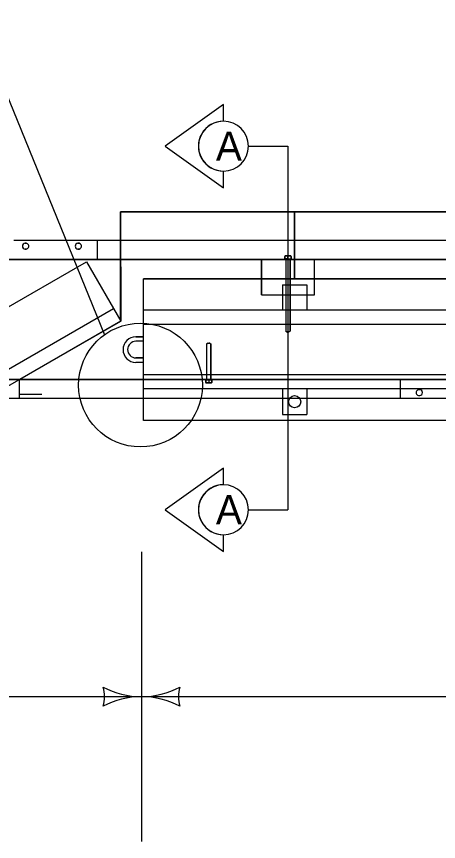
# Model space of a CAD drawing. Extents: x -2137026 to -2131464, y -2138478 to -2136524.
# Drawn here: x -2136746.1 to -2136526.6, y -2137925.1 to -2137495.8 of the extents above; entities that cross this region are included whole.
import ezdxf

# ---------------------------------------------------------------- set-up
doc = ezdxf.new("R2010")
doc.units = 0
for name, color, linetype in [('conPaving', 7, 'Continuous'), ('Level 2', 7, 'Continuous'), ('Level 3', 7, 'Continuous'), ('Level 41', 7, 'Continuous'), ('Level 9', 7, 'Continuous')]:
    doc.layers.add(name, color=color, linetype=linetype)

msp = doc.modelspace()

# ---------------------------------------------------------------- linework, layer by layer
at = {"layer": 'conPaving'}
for p, q in [((-2136462.32, -2137612.31), (-2136747.4, -2137612.31)), ((-2136741.63, -2137613.85), (-2136740.97, -2137613.85)), ((-2136740.97, -2137616.82), (-2136741.63, -2137616.82)), ((-2136714.21, -2137613.85), (-2136713.54, -2137613.85)), ((-2136713.54, -2137616.82), (-2136714.21, -2137616.82)), ((-2136606.45, -2137621.92), (-2136606.85, -2137621.92)), ((-2136606.85, -2137621.92), (-2136606.85, -2137622.22)), ((-2136606.45, -2137620.66), (-2136606.45, -2137621.92)), ((-2136604.57, -2137620.35), (-2136606.17, -2137620.35)), ((-2136603.55, -2137620.35), (-2136604.57, -2137620.35)), ((-2136603.26, -2137621.92), (-2136603.26, -2137620.66)), ((-2136602.87, -2137621.92), (-2136603.26, -2137621.92)), ((-2136602.87, -2137622.22), (-2136602.87, -2137621.92)), ((-2136768.45, -2137622.22), (-2136441.26, -2137622.22)), ((-2136606.85, -2137622.22), (-2136605.92, -2137622.22)), ((-2136605.92, -2137622.22), (-2136605.92, -2137659.5)), ((-2136603.8, -2137659.5), (-2136603.8, -2137622.22)), ((-2136603.8, -2137622.22), (-2136602.87, -2137622.22)), ((-2136605.92, -2137659.5), (-2136604.85, -2137660.28)), ((-2136604.85, -2137660.27), (-2136603.8, -2137659.5)), ((-2136604.85, -2137660.28), (-2136604.85, -2137660.25)), ((-2136604.85, -2137660.25), (-2136604.85, -2137660.27)), ((-2136683.95, -2137662.47), (-2136680.02, -2137662.47)), ((-2136647.12, -2137666.16), (-2136646.59, -2137665.78)), ((-2136647.12, -2137684.65), (-2136647.12, -2137666.16)), ((-2136646.59, -2137665.78), (-2136646.06, -2137665.78)), ((-2136646.06, -2137665.78), (-2136645.53, -2137665.78)), ((-2136645.53, -2137665.78), (-2136645, -2137666.16)), ((-2136645, -2137666.16), (-2136645, -2137684.65)), ((-2136680.02, -2137675.83), (-2136683.95, -2137675.83)), ((-2136809.17, -2137684.65), (-2136481.98, -2137684.65)), ((-2136648.05, -2137684.95), (-2136648.05, -2137684.65)), ((-2136648.05, -2137684.65), (-2136647.12, -2137684.65)), ((-2136647.65, -2137684.95), (-2136648.05, -2137684.95)), ((-2136647.65, -2137686.21), (-2136647.65, -2137684.95)), ((-2136645.77, -2137686.52), (-2136647.37, -2137686.52)), ((-2136644.75, -2137686.52), (-2136645.77, -2137686.52)), ((-2136645, -2137684.65), (-2136644.07, -2137684.65)), ((-2136644.07, -2137684.95), (-2136644.46, -2137684.95)), ((-2136644.46, -2137684.95), (-2136644.46, -2137686.21)), ((-2136644.07, -2137684.65), (-2136644.07, -2137684.95)), ((-2136536.22, -2137690.05), (-2136536.89, -2137690.05)), ((-2136503.04, -2137694.56), (-2136788.12, -2137694.56)), ((-2136536.89, -2137693.02), (-2136536.22, -2137693.02))]:
    msp.add_line(p, q, dxfattribs=at)
for points in [[(-2136680.02, -2137662.47), (-2136680.02, -2137632.29), (-2136601.44, -2137632.29), (-2136601.44, -2137597.41), (-2136691.9, -2137597.41), (-2136691.85, -2137654.33)], [(-2136691.85, -2137654.33), (-2136744.37, -2137684.65), (-2136680.02, -2137684.65), (-2136680.02, -2137675.83)]]:
    msp.add_lwpolyline(points, dxfattribs=at)
msp.add_arc((-2136683.95, -2137669.15), 6.68, 90, 270, dxfattribs=at)
for centre, major_axis, start_param, end_param in [((-2136741.63, -2137615.33), (0, -1.49), 3.141593, 6.283185), ((-2136740.97, -2137615.33), (0, -1.49), 0, 3.141593), ((-2136714.21, -2137615.33), (0, -1.49), 3.141593, 6.283185), ((-2136713.54, -2137615.33), (0, -1.49), 0, 3.141593), ((-2136606.17, -2137620.66), (0, 0.315), 0, 1.570796), ((-2136603.55, -2137620.66), (0, 0.315), 4.712389, 6.283185), ((-2136647.37, -2137686.21), (0, -0.315), 4.712389, 6.283185), ((-2136644.75, -2137686.21), (0, -0.315), 6.283185, 7.853982), ((-2136536.89, -2137691.53), (0, 1.49), 0, 3.141593), ((-2136536.22, -2137691.53), (0, 1.49), 3.141593, 6.283185)]:
    msp.add_ellipse(centre, major_axis=major_axis, ratio=0.899999, start_param=start_param, end_param=end_param, dxfattribs=at)
at = {"layer": 'Level 2'}
for p, q in [((-2136767.77, -2137495.85), (-2136700.29, -2137661.41)), ((-2136625.44, -2137563.31), (-2136604.87, -2137563.31)), ((-2136604.87, -2137563.31), (-2136604.87, -2137752.45)), ((-2136762.17, -2137653.8), (-2136709.66, -2137623.48)), ((-2136709.66, -2137623.48), (-2136691.85, -2137654.33)), ((-2136188.5, -2137632.29), (-2136680.02, -2137632.29)), ((-2136680.02, -2137706.01), (-2136680.02, -2137632.29)), ((-2136754.92, -2137682), (-2136695.64, -2137647.78)), ((-2136188.5, -2137648.67), (-2136680.02, -2137648.67)), ((-2136752.91, -2137689.58), (-2136691.85, -2137654.33)), ((-2136188.5, -2137656.04), (-2136680.02, -2137656.04)), ((-2136188.5, -2137682.26), (-2136680.02, -2137682.26)), ((-2136188.5, -2137689.63), (-2136680.02, -2137689.63)), ((-2136188.5, -2137706.01), (-2136680.02, -2137706.01)), ((-2136625.44, -2137752.45), (-2136604.87, -2137752.45)), ((-2136681.05, -2137774.34), (-2136681.05, -2137925.06)), ((-2136777.98, -2137849.7), (-2136681.05, -2137849.7)), ((-2136681.05, -2137849.7), (-2136429.72, -2137849.7))]:
    msp.add_line(p, q, dxfattribs=at)
for centre, radius, start, end in [((-2136716.68, -2137849.7), 16.42, 342.2667, 17.7334), ((-2136681.05, -2137807.2), 42.5, 241.9275, 270), ((-2136681.05, -2137807.2), 42.5, 270, 298.0725), ((-2136645.41, -2137849.7), 16.42, 162.2666, 197.7334), ((-2136681.05, -2137892.2), 42.5, 90, 118.0725), ((-2136681.05, -2137892.2), 42.5, 61.9275, 90)]:
    msp.add_arc(centre, radius, start, end, dxfattribs=at)
at = {"layer": 'Level 3'}
for p, q in [((-2136638.43, -2137541.64), (-2136668.77, -2137563.31)), ((-2136638.43, -2137550.31), (-2136638.43, -2137541.64)), ((-2136668.77, -2137563.31), (-2136638.43, -2137584.97)), ((-2136638.43, -2137584.97), (-2136638.43, -2137576.31)), ((-2136638.43, -2137730.79), (-2136668.77, -2137752.45)), ((-2136638.43, -2137739.45), (-2136638.43, -2137730.79)), ((-2136668.77, -2137752.45), (-2136638.43, -2137774.12)), ((-2136638.43, -2137774.12), (-2136638.43, -2137765.46))]:
    msp.add_line(p, q, dxfattribs=at)
for centre, start, end in [((-2136638.44, -2137563.31), 89.9948, 270.0052), ((-2136638.43, -2137563.31), 90.0052, 269.9948), ((-2136638.44, -2137563.31), 270.0052, 89.9948), ((-2136638.44, -2137752.45), 89.9948, 270.0052), ((-2136638.43, -2137752.45), 90.0052, 269.9948), ((-2136638.44, -2137752.45), 270.0052, 89.9948)]:
    msp.add_arc(centre, 13, start, end, dxfattribs=at)
at = {"layer": 'Level 41'}
for p, q in [((-2136607.67, -2137635.41), (-2136595.09, -2137635.41)), ((-2136607.67, -2137635.41), (-2136607.67, -2137648.67)), ((-2136595.09, -2137635.41), (-2136595.09, -2137648.67)), ((-2136680.02, -2137662.47), (-2136683.95, -2137662.47)), ((-2136680.02, -2137664.82), (-2136683.95, -2137664.82)), ((-2136680.02, -2137673.48), (-2136683.95, -2137673.48)), ((-2136680.02, -2137675.83), (-2136683.95, -2137675.83)), ((-2136607.67, -2137689.63), (-2136607.67, -2137702.89)), ((-2136595.09, -2137689.63), (-2136595.09, -2137702.89)), ((-2136607.67, -2137702.89), (-2136595.09, -2137702.89))]:
    msp.add_line(p, q, dxfattribs=at)
msp.add_circle((-2136601.38, -2137696.26), 3.15, dxfattribs=at)
for radius in [6.68, 4.33]:
    msp.add_arc((-2136683.95, -2137669.15), radius, 90, 270, dxfattribs=at)
at = {"layer": 'Level 9'}
for p, q in [((-2136691.9, -2137654.26), (-2136691.9, -2137597.41)), ((-2136691.9, -2137597.41), (-2134672.37, -2137597.41)), ((-2136191.5, -2137597.41), (-2136601.44, -2137597.41)), ((-2136601.44, -2137597.41), (-2136601.44, -2137632.29)), ((-2136462.32, -2137612.31), (-2136747.4, -2137612.31)), ((-2136703.98, -2137622.22), (-2136703.98, -2137612.31)), ((-2136604.86, -2137621.92), (-2136606.85, -2137621.92)), ((-2136606.85, -2137621.92), (-2136606.85, -2137622.22)), ((-2136606.45, -2137621.92), (-2136606.45, -2137620.66)), ((-2136606.45, -2137621.92), (-2136603.26, -2137621.92)), ((-2136606.17, -2137620.35), (-2136605.14, -2137620.35)), ((-2136605.14, -2137620.35), (-2136603.55, -2137620.35)), ((-2136604.86, -2137621.92), (-2136604.86, -2137620.66)), ((-2136604.86, -2137621.92), (-2136602.87, -2137621.92)), ((-2136603.26, -2137620.66), (-2136603.26, -2137621.92)), ((-2136602.87, -2137622.22), (-2136602.87, -2137621.92)), ((-2136407.43, -2137622.22), (-2136802.28, -2137622.22)), ((-2136618.61, -2137622.22), (-2136618.61, -2137640.62)), ((-2136591.1, -2137622.22), (-2136618.61, -2137622.22)), ((-2136618.61, -2137640.62), (-2136618.61, -2137622.22)), ((-2136606.85, -2137622.22), (-2136602.87, -2137622.22)), ((-2136605.92, -2137622.22), (-2136605.92, -2137659.5)), ((-2136604.86, -2137622.22), (-2136603.8, -2137622.22)), ((-2136603.8, -2137622.22), (-2136603.8, -2137640.62)), ((-2136603.8, -2137622.22), (-2136603.8, -2137659.5)), ((-2136591.1, -2137640.62), (-2136591.1, -2137622.22)), ((-2136591.1, -2137640.62), (-2136591.1, -2137622.22)), ((-2136601.44, -2137632.29), (-2136188.5, -2137632.29)), ((-2136618.61, -2137640.62), (-2136591.1, -2137640.62)), ((-2136618.61, -2137640.62), (-2136591.1, -2137640.62)), ((-2136605.39, -2137659.89), (-2136605.92, -2137659.5)), ((-2136605.39, -2137659.89), (-2136604.86, -2137659.89)), ((-2136604.33, -2137659.89), (-2136604.86, -2137659.89)), ((-2136604.33, -2137659.89), (-2136603.8, -2137659.5)), ((-2136680.02, -2137664.82), (-2136683.95, -2137664.82)), ((-2136680.02, -2137673.48), (-2136680.02, -2137664.82)), ((-2136646.59, -2137665.78), (-2136647.12, -2137666.16)), ((-2136647.12, -2137684.65), (-2136647.12, -2137666.16)), ((-2136646.59, -2137665.78), (-2136646.06, -2137665.78)), ((-2136645.53, -2137665.78), (-2136646.06, -2137665.78)), ((-2136645.53, -2137665.78), (-2136645, -2137666.16)), ((-2136645, -2137684.65), (-2136645, -2137666.16)), ((-2136683.95, -2137673.48), (-2136680.02, -2137673.48)), ((-2136448.15, -2137684.65), (-2136843, -2137684.65)), ((-2136744.7, -2137684.65), (-2136744.7, -2137694.56)), ((-2136648.05, -2137684.95), (-2136648.05, -2137684.65)), ((-2136648.05, -2137684.65), (-2136644.07, -2137684.65)), ((-2136646.06, -2137684.95), (-2136648.05, -2137684.95)), ((-2136647.65, -2137684.95), (-2136644.46, -2137684.95)), ((-2136647.65, -2137684.95), (-2136647.65, -2137686.21)), ((-2136647.37, -2137686.52), (-2136646.34, -2137686.52)), ((-2136646.34, -2137686.52), (-2136644.75, -2137686.52)), ((-2136646.06, -2137684.65), (-2136645, -2137684.65)), ((-2136646.06, -2137684.95), (-2136644.07, -2137684.95)), ((-2136646.06, -2137684.95), (-2136646.06, -2137686.21)), ((-2136644.46, -2137686.21), (-2136644.46, -2137684.95)), ((-2136644.07, -2137684.65), (-2136644.07, -2137684.95)), ((-2136546.45, -2137684.65), (-2136546.45, -2137694.56)), ((-2136503.04, -2137694.56), (-2136788.12, -2137694.56)), ((-2136744.71, -2137692.38), (-2136732.83, -2137692.38))]:
    msp.add_line(p, q, dxfattribs=at)
for points in [[(-2136740.97, -2137613.85), (-2136741.63, -2137613.85)], [(-2136741.63, -2137616.82), (-2136740.97, -2137616.82)], [(-2136713.54, -2137613.85), (-2136714.21, -2137613.85)], [(-2136714.21, -2137616.82), (-2136713.54, -2137616.82)], [(-2136536.22, -2137690.05), (-2136536.89, -2137690.05)], [(-2136536.89, -2137693.02), (-2136536.22, -2137693.02)]]:
    msp.add_lwpolyline(points, dxfattribs=at)
msp.add_circle((-2136681.56, -2137687.6), 32.2, dxfattribs=at)
msp.add_arc((-2136683.95, -2137669.15), 4.33, 90, 270, dxfattribs=at)
for centre, major_axis, start_param, end_param in [((-2136741.63, -2137615.33), (0, -1.49), 3.141593, 6.283185), ((-2136740.97, -2137615.33), (0, -1.49), 0, 3.141593), ((-2136714.21, -2137615.33), (0, -1.49), 3.141593, 6.283185), ((-2136713.54, -2137615.33), (0, -1.49), 0, 3.141593), ((-2136606.17, -2137620.66), (0, 0.315), 6.283185, 7.853982), ((-2136605.14, -2137620.66), (0, 0.315), 4.712389, 6.283185), ((-2136604.57, -2137620.66), (0, 0.315), 0, 1.570796), ((-2136603.55, -2137620.66), (0, 0.315), 4.712389, 6.283185), ((-2136647.37, -2137686.21), (0, 0.315), 1.570796, 3.141593), ((-2136646.34, -2137686.21), (0, 0.315), 3.141593, 4.712389), ((-2136645.77, -2137686.21), (0, 0.315), 1.570796, 3.141593), ((-2136644.75, -2137686.21), (0, 0.315), 3.141593, 4.712389), ((-2136536.89, -2137691.53), (0, 1.49), 0, 3.141593), ((-2136536.22, -2137691.53), (0, 1.49), 3.141593, 6.283185)]:
    msp.add_ellipse(centre, major_axis=major_axis, ratio=0.899999, start_param=start_param, end_param=end_param, dxfattribs=at)

# ---------------------------------------------------------------- texts
at = {"layer": 'Level 3'}
for p in [(-2136642.36, -2137570.91), (-2136642.36, -2137760.06)]:
    msp.add_text('A', height=15.2, dxfattribs=at).set_placement(p)

doc.saveas('drawing.dxf')
